// Mitsubishi GX Works2 project: code_plc_misu_dengiaothong6d   PLC: FX1S

PROGRAM MAIN
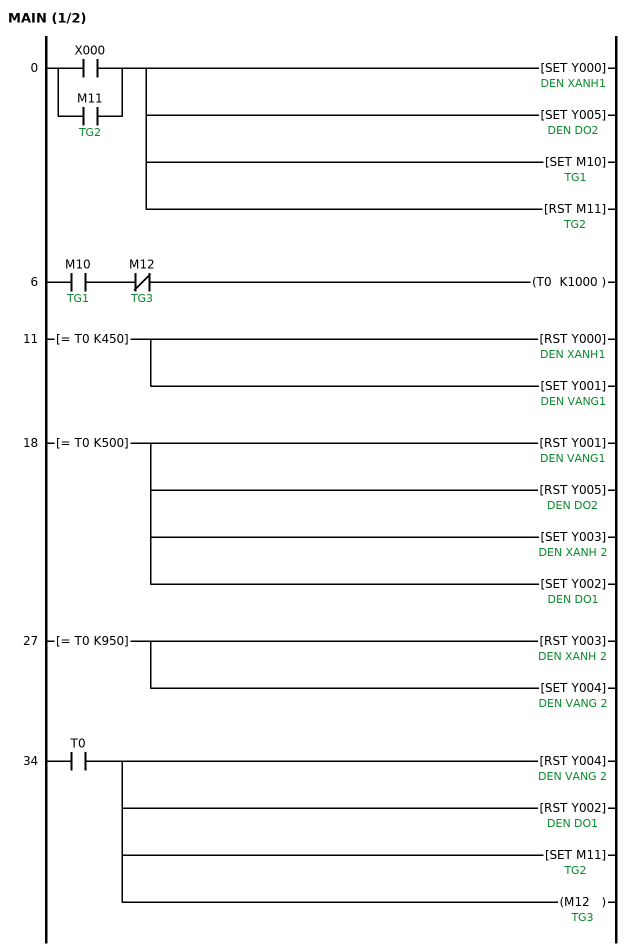
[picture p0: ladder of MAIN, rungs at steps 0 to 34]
0     LD      X000
      OR      M11  ; TG2
      SET     Y000  ; DEN XANH1
      SET     Y005  ; DEN DO2
      SET     M10  ; TG1
      RST     M11  ; TG2
6     LD      M10  ; TG1
      ANI     M12  ; TG3
      OUT     T0 K1000
11    LD=     T0 K450
      RST     Y000  ; DEN XANH1
      SET     Y001  ; DEN VANG1
18    LD=     T0 K500
      RST     Y001  ; DEN VANG1
      RST     Y005  ; DEN DO2
      SET     Y003  ; DEN XANH 2
      SET     Y002  ; DEN DO1
27    LD=     T0 K950
      RST     Y003  ; DEN XANH 2
      SET     Y004  ; DEN VANG 2
34    LD      T0
      RST     Y004  ; DEN VANG 2
      RST     Y002  ; DEN DO1
      SET     M11  ; TG2
      OUT     M12  ; TG3
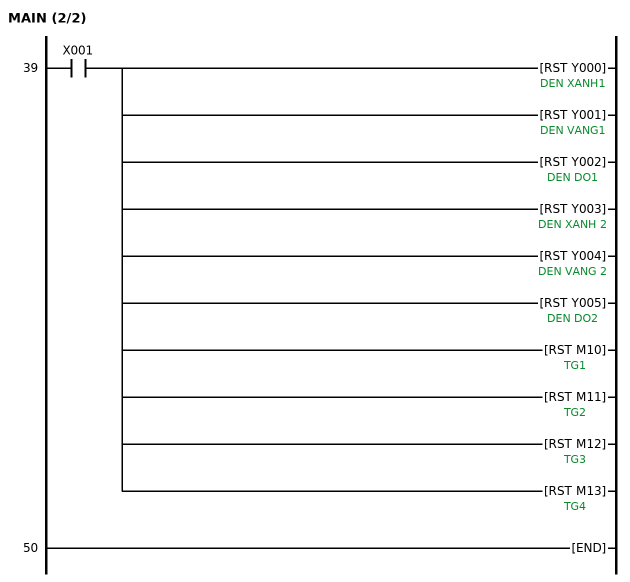
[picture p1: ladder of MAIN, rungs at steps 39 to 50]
39    LD      X001
      RST     Y000  ; DEN XANH1
      RST     Y001  ; DEN VANG1
      RST     Y002  ; DEN DO1
      RST     Y003  ; DEN XANH 2
      RST     Y004  ; DEN VANG 2
      RST     Y005  ; DEN DO2
      RST     M10  ; TG1
      RST     M11  ; TG2
      RST     M12  ; TG3
      RST     M13  ; TG4
50    END
END_PROGRAM
